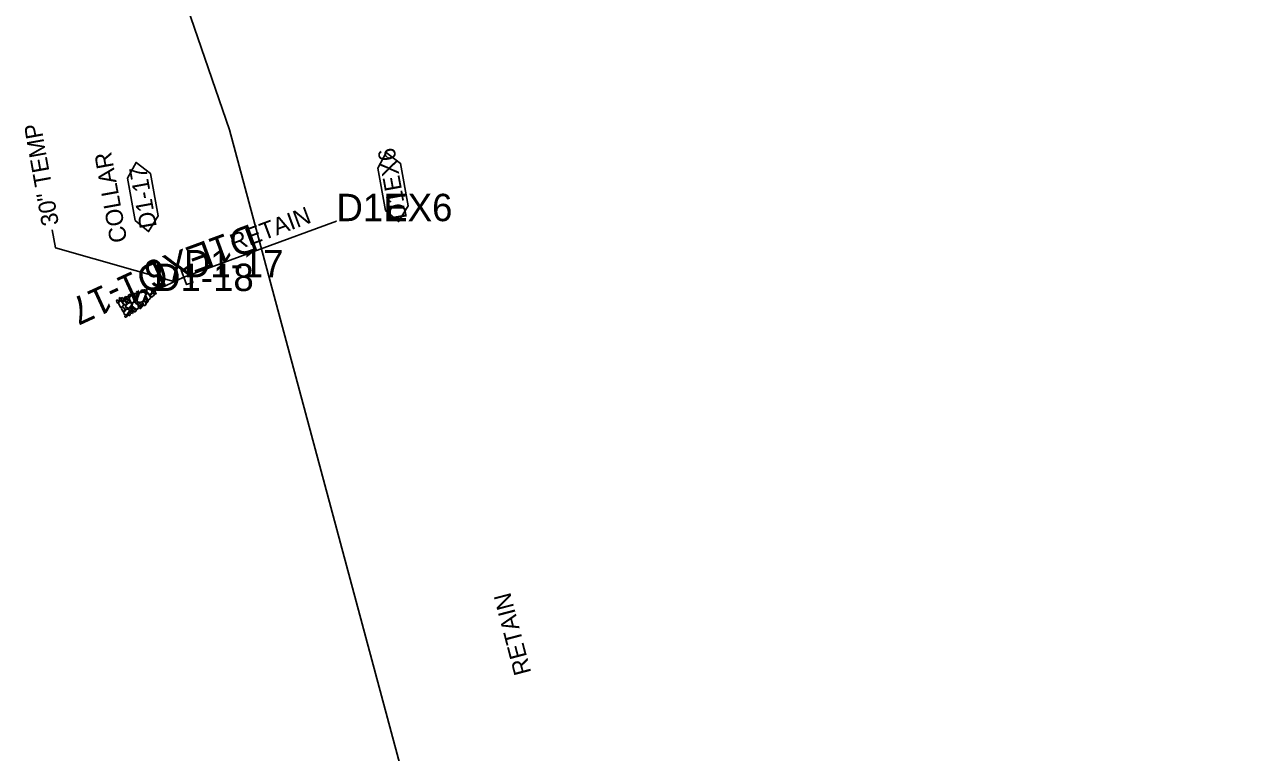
# Model space of a CAD drawing. Extents: x 465700 to 483515, y 488970 to 507540.
# Drawn here: x 481181.7 to 481540.6, y 491956.4 to 492169 of the extents above; entities that cross this region are included whole.
import ezdxf

# ---------------------------------------------------------------- set-up
doc = ezdxf.new("R2010")
doc.units = 0
for name, color, linetype in [('Exist Plan Preparation Watershed Blue', 7, 'Continuous'), ('Prop Drainage Structure Box Number Symbol CELL', 7, 'Continuous'), ('Prop Drainage Structure Pipe Collar CELL', 7, 'Continuous'), ('Prop Drainage Structure Pipe Collar Label', 7, 'Continuous'), ('Prop Drainage Structure Pipe RCP 30in Class III', 7, 'Continuous'), ('Prop Drainage Structure Pipe RCP 30in Class III Label', 7, 'Continuous'), ('Prop Drainage Structure Pipe Stub Out CELL', 7, 'Continuous'), ('Prop Erosion Rip Rap Pad at Outlet CELL', 7, 'Continuous'), ('Prop NEU Channel Block Detail Label', 7, 'Continuous'), ('Scratch_Level_8', 7, 'Continuous')]:
    doc.layers.add(name, color=color, linetype=linetype)

msp = doc.modelspace()

# ---------------------------------------------------------------- linework, layer by layer
at = {"layer": 'Exist Plan Preparation Watershed Blue'}
msp.add_lwpolyline([(481914.1, 492508.16), (481856.26, 492637.66), (481730.25, 492750.66), (481730.25, 492750.66), (481669.43, 492692.33), (481584.65, 492614.4), (481584.65, 492614.4), (481584.65, 492614.4), (481329.7, 492355.65), (481209.8, 492230.86), (481241.6, 492138.31), (481300.91, 491917.87), (481327.1, 491923.15), (481339.19, 491872.39), (481355.48, 491803.22), (481355.48, 491803.22), (481355.48, 491803.22)], dxfattribs=at)
at = {"layer": 'Prop Drainage Structure Box Number Symbol CELL'}
for points in [[(481287.19, 492114.7), (481284.94, 492127.1), (481287.38, 492131.71), (481291.61, 492128.47), (481293.86, 492116.07), (481291.06, 492111.5), (481287.19, 492114.7)], [(481214.11, 492111.78), (481211.86, 492124.18), (481214.31, 492128.8), (481218.53, 492125.56), (481220.78, 492113.15), (481217.98, 492108.58), (481214.11, 492111.78)]]:
    msp.add_lwpolyline(points, dxfattribs=at)
at = {"layer": 'Prop Drainage Structure Pipe Collar CELL'}
msp.add_line((481228.3, 492095.22), (481228.3, 492095.22), dxfattribs=at)
msp.add_line((481228.3, 492095.22), (481228.3, 492095.22), dxfattribs=at)
msp.add_lwpolyline([(481227.53, 492097.35), (481229.39, 492098.02), (481230.93, 492093.75), (481229.07, 492093.08)], close=True, dxfattribs=at)
msp.add_lwpolyline([(481227.58, 492094.95), (481228.3, 492095.22), (481227.53, 492097.35), (481229.39, 492098.02), (481230.93, 492093.75), (481229.07, 492093.08), (481229.07, 492093.08), (481228.3, 492095.22)], dxfattribs=at)
at = {"layer": 'Prop Drainage Structure Pipe RCP 30in Class III'}
msp.add_line((481228.3, 492095.22), (481219.59, 492091.21), dxfattribs=at)
at = {"layer": 'Prop Drainage Structure Pipe Stub Out CELL'}
msp.add_line((481272.89, 492111.62), (481272.89, 492111.62), dxfattribs=at)
msp.add_line((481272.89, 492111.62), (481272.89, 492111.62), dxfattribs=at)
msp.add_lwpolyline([(481272.9, 492111.63), (481272.89, 492111.61), (481272.87, 492111.62), (481272.88, 492111.64), (481272.9, 492111.63)], dxfattribs=at)
at = {"layer": 'Prop Erosion Rip Rap Pad at Outlet CELL'}
msp.add_line((481219.59, 492091.21), (481219.59, 492091.21), dxfattribs=at)
msp.add_line((481219.59, 492091.21), (481219.59, 492091.21), dxfattribs=at)
for points in [[(481217.86, 492092.09), (481218.22, 492091.84), (481218.99, 492091.15), (481218.84, 492090.45), (481218.36, 492090.22), (481217.5, 492091.09), (481217.46, 492091.73), (481217.75, 492092.03)], [(481219.33, 492091.06), (481219.16, 492091.21), (481218.71, 492091.51), (481218.86, 492091.83), (481219.02, 492091.92), (481219.57, 492091.54), (481219.59, 492091.21), (481219.33, 492091.06)], [(481208.88, 492088.65), (481209.11, 492088.44), (481209.39, 492088.04), (481209.16, 492087.77), (481208.9, 492087.7), (481208.63, 492088.28), (481208.71, 492088.58), (481208.88, 492088.65)], [(481209.85, 492088.45), (481210.18, 492088.04), (481210.71, 492087.22), (481210.28, 492086.56), (481209.75, 492086.5), (481209.2, 492087.57), (481209.4, 492088.17), (481209.85, 492088.45)], [(481209.67, 492089.29), (481209.89, 492089.08), (481210.18, 492088.68), (481209.94, 492088.41), (481209.68, 492088.34), (481209.42, 492088.92), (481209.49, 492089.22), (481209.67, 492089.29)], [(481210.36, 492089.33), (481210.59, 492089.11), (481210.88, 492088.72), (481210.64, 492088.45), (481210.38, 492088.37), (481210.12, 492088.96), (481210.19, 492089.26), (481210.36, 492089.33)], [(481211.24, 492087.01), (481210.91, 492087.21), (481210.43, 492087.76), (481210.54, 492088.17), (481210.81, 492088.31), (481211.41, 492087.73), (481211.51, 492087.35), (481211.24, 492087.01)], [(481210.79, 492088.92), (481210.92, 492089.23), (481211.26, 492089.6), (481211.54, 492089.5), (481211.63, 492089.35), (481211.23, 492088.83), (481210.98, 492088.82), (481210.79, 492088.92)], [(481211.12, 492088.29), (481211.25, 492088.45), (481211.56, 492088.88), (481211.92, 492088.74), (481212.01, 492088.57), (481211.58, 492088.05), (481211.33, 492088.15), (481211.12, 492088.29)], [(481212.16, 492088.69), (481211.99, 492088.83), (481211.65, 492089.2), (481211.72, 492089.5), (481211.85, 492089.59), (481212.3, 492089.28), (481212.35, 492088.97), (481212.24, 492088.78)], [(481211.75, 492087.85), (481211.82, 492088.16), (481212.18, 492088.5), (481212.49, 492088.41), (481212.56, 492088.24), (481212.17, 492087.79), (481211.94, 492087.74), (481211.75, 492087.85)], [(481211.98, 492089.61), (481212.02, 492089.89), (481212.38, 492090.24), (481212.69, 492090.16), (481212.78, 492089.99), (481212.39, 492089.5), (481212.14, 492089.48), (481211.98, 492089.61)], [(481213.02, 492089.8), (481213.38, 492089.4), (481213.82, 492088.48), (481213.45, 492087.91), (481212.92, 492087.79), (481212.39, 492088.87), (481212.54, 492089.58), (481213.02, 492089.8)], [(481212.96, 492089.95), (481213, 492090.24), (481213.37, 492090.59), (481213.67, 492090.5), (481213.77, 492090.34), (481213.37, 492089.84), (481213.12, 492089.83), (481212.96, 492089.95)], [(481213.89, 492089.16), (481213.69, 492089.29), (481213.26, 492089.61), (481213.45, 492089.94), (481213.59, 492090.02), (481214.09, 492089.62), (481214.1, 492089.41), (481213.89, 492089.16)], [(481214.06, 492090.58), (481214.4, 492090.44), (481214.92, 492089.96), (481214.82, 492089.52), (481214.56, 492089.37), (481213.88, 492089.91), (481213.85, 492090.34), (481214.06, 492090.58)], [(481213.86, 492088.72), (481213.89, 492089), (481214.28, 492089.32), (481214.56, 492089.28), (481214.67, 492089.09), (481214.27, 492088.61), (481214.01, 492088.6), (481213.86, 492088.72)], [(481214.39, 492088.45), (481214.64, 492088.25), (481214.76, 492087.84), (481214.57, 492087.5), (481214.35, 492087.51), (481214.04, 492088.02), (481214.22, 492088.36), (481214.39, 492088.45)], [(481214.75, 492091.12), (481214.97, 492090.9), (481215.26, 492090.5), (481215.02, 492090.24), (481214.76, 492090.16), (481214.5, 492090.74), (481214.57, 492091.05), (481214.75, 492091.12)], [(481214.64, 492088.28), (481214.7, 492089.13), (481215.38, 492090.73), (481216.59, 492090.84), (481217.19, 492090.29), (481216.4, 492088.28), (481215.5, 492087.88), (481214.59, 492088.12)], [(481215.58, 492090.92), (481215.68, 492091.2), (481216.04, 492091.55), (481216.33, 492091.5), (481216.44, 492091.31), (481215.99, 492090.82), (481215.77, 492090.81), (481215.58, 492090.92)], [(481216.3, 492090.97), (481216.34, 492091.25), (481216.7, 492091.6), (481217.01, 492091.52), (481217.1, 492091.36), (481216.7, 492090.87), (481216.46, 492090.84), (481216.3, 492090.97)], [(481216.65, 492088.89), (481216.69, 492089.18), (481217.06, 492089.52), (481217.36, 492089.46), (481217.42, 492089.28), (481217.04, 492088.82), (481216.84, 492088.79), (481216.65, 492088.89)], [(481216.7, 492088.3), (481216.78, 492088.61), (481217.16, 492088.91), (481217.45, 492088.88), (481217.56, 492088.68), (481217.11, 492088.19), (481216.89, 492088.2), (481216.7, 492088.3)], [(481217.25, 492091.34), (481217.38, 492091.15), (481217.61, 492090.77), (481217.41, 492090.51), (481217.25, 492090.42), (481216.94, 492090.93), (481216.98, 492091.3), (481217.25, 492091.34)], [(481217.11, 492087.87), (481217.14, 492088.17), (481217.51, 492088.51), (481217.82, 492088.44), (481217.88, 492088.26), (481217.49, 492087.81), (481217.3, 492087.77), (481217.11, 492087.87)], [(481217.72, 492090.57), (481218.07, 492090.21), (481218.6, 492089.35), (481218.19, 492088.7), (481217.74, 492088.65), (481217.17, 492089.75), (481217.32, 492090.32), (481217.72, 492090.57)], [(481218.41, 492089.73), (481218.57, 492090.04), (481218.97, 492090.54), (481219.5, 492090.45), (481219.71, 492090.11), (481219.04, 492089.48), (481218.68, 492089.5), (481218.41, 492089.73)], [(481219.96, 492090.26), (481219.77, 492090.41), (481219.31, 492090.75), (481219.49, 492091.02), (481219.65, 492091.13), (481220.15, 492090.76), (481220.22, 492090.42), (481219.96, 492090.26)], [(481210.51, 492086.56), (481210.76, 492086.28), (481211.08, 492085.74), (481210.73, 492085.29), (481210.45, 492085.21), (481210.06, 492086.07), (481210.2, 492086.43), (481210.51, 492086.56)], [(481212.45, 492085.51), (481212.26, 492085.04), (481211.57, 492084.28), (481210.87, 492084.42), (481210.71, 492084.93), (481211.57, 492085.82), (481212.06, 492085.88), (481212.52, 492085.55)], [(481210.97, 492085.8), (481211.02, 492086.09), (481211.38, 492086.45), (481211.69, 492086.37), (481211.78, 492086.21), (481211.38, 492085.7), (481211.13, 492085.68), (481210.97, 492085.8)], [(481213.13, 492087.35), (481212.87, 492086.99), (481212.16, 492086.21), (481211.5, 492086.38), (481211.22, 492086.83), (481212.11, 492087.67), (481212.71, 492087.85), (481213.04, 492087.43)], [(481212.28, 492084.98), (481212.53, 492084.78), (481212.64, 492084.37), (481212.44, 492084.04), (481212.23, 492084.04), (481211.92, 492084.56), (481212.12, 492084.89), (481212.28, 492084.98)], [(481212.5, 492086.1), (481212.55, 492086.35), (481212.93, 492086.77), (481213.24, 492086.68), (481213.3, 492086.5), (481212.91, 492086), (481212.71, 492085.96), (481212.5, 492086.1)], [(481213.31, 492084.66), (481212.99, 492084.78), (481212.69, 492085.12), (481212.71, 492085.44), (481212.96, 492085.6), (481213.34, 492085.13), (481213.43, 492084.83), (481213.31, 492084.66)], [(481213.4, 492086.37), (481213.66, 492086.17), (481213.78, 492085.77), (481213.58, 492085.42), (481213.36, 492085.43), (481213.05, 492085.94), (481213.24, 492086.28), (481213.4, 492086.37)], [(481214.54, 492085.9), (481214.07, 492086.16), (481213.11, 492086.87), (481213.4, 492087.78), (481213.82, 492088.04), (481214.91, 492087.03), (481215.02, 492086.28), (481214.61, 492085.8)], [(481213.69, 492085.24), (481213.72, 492085.53), (481214.09, 492085.87), (481214.39, 492085.82), (481214.45, 492085.64), (481214.08, 492085.18), (481213.89, 492085.14), (481213.69, 492085.24)], [(481215, 492087.17), (481215.06, 492087.44), (481215.43, 492087.75), (481215.73, 492087.71), (481215.84, 492087.51), (481215.41, 492087.06), (481215.19, 492087.07), (481215, 492087.17)], [(481215.66, 492086.08), (481215.4, 492086.15), (481215.09, 492086.44), (481215.1, 492086.8), (481215.38, 492086.97), (481215.75, 492086.49), (481215.81, 492086.18), (481215.66, 492086.08)], [(481215.64, 492086.66), (481215.69, 492086.95), (481216.06, 492087.29), (481216.35, 492087.23), (481216.41, 492087.04), (481216.04, 492086.59), (481215.84, 492086.56), (481215.64, 492086.66)], [(481216.69, 492088.27), (481217, 492087.98), (481217.31, 492087.47), (481216.98, 492087.01), (481216.64, 492086.98), (481216.27, 492087.77), (481216.44, 492088.13), (481216.69, 492088.27)], [(481211.01, 492083.7), (481211.05, 492083.99), (481211.42, 492084.33), (481211.73, 492084.26), (481211.79, 492084.08), (481211.42, 492083.62), (481211.22, 492083.6), (481211.01, 492083.7)]]:
    msp.add_lwpolyline(points, dxfattribs=at)
at = {"layer": 'Prop NEU Channel Block Detail Label'}
msp.add_lwpolyline([(481225.32, 492093.99), (481190.75, 492103.85), (481189.81, 492109.06)], dxfattribs=at)
at = {"layer": 'Scratch_Level_8'}
for p, q in [((481272.89, 492111.62), (481228.3, 492095.22)), ((481228.3, 492095.22), (481219.59, 492091.21))]:
    msp.add_line(p, q, dxfattribs=at)

# ---------------------------------------------------------------- texts
at = {"layer": 'Prop Drainage Structure Box Number Symbol CELL'}
for s, p in [('D1EX6', (481293.58, 492112.48)), ('D1-17', (481220.42, 492110.03))]:
    msp.add_text(s, height=5, rotation=100.2925, dxfattribs=at).set_placement(p)
at = {"layer": 'Prop Drainage Structure Pipe Collar Label'}
for s, rotation, p in [('COLLAR', 100.2896, (481211.78, 492105.81)), ('RETAIN', 20.4277, (481242.9, 492102.74)), ('RETAIN', 104.6938, (481329.84, 491979.76))]:
    msp.add_text(s, height=5, rotation=rotation, dxfattribs=at).set_placement(p)
at = {"layer": 'Prop Drainage Structure Pipe RCP 30in Class III Label'}
msp.add_text('30" TEMP', height=5, rotation=100.1916, dxfattribs=at).set_placement((481191.8, 492110.73))
at = {"layer": 'Prop Drainage Structure Pipe Stub Out CELL'}
msp.add_text('SO', height=0.0104, rotation=194.8977, dxfattribs=at).set_placement((481272.89, 492111.63))
at = {"layer": 'Scratch_Level_8'}
for s, p in [('D1EX6', (481272.89, 492111.62)), ('D1-17', (481228.3, 492095.22)), ('D1-18', (481219.59, 492091.21))]:
    msp.add_text(s, height=8, dxfattribs=at).set_placement(p)
for s, rotation, p in [('D1EX6', 200.2033, (481247.83, 492110.93)), ('D1-17', 204.7058, (481220.6, 492100.48))]:
    msp.add_text(s, height=8, rotation=rotation, dxfattribs=at).set_placement(p)

doc.saveas('drawing.dxf')
